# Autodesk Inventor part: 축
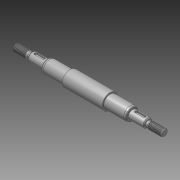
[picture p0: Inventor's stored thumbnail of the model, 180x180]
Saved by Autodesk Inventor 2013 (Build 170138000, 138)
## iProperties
Created: 2015-11
Part Number: 축
Material: 강철, 연강
Document SubType Name: Modeling
Designer: mduedu
Density: 7.86 g/cm^3
Mass: 198.507 g
Surface Area: 75.8873 cm^2
Volume: 25.2553 cm^3
Author: mduedu
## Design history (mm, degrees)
sketch "스케치1"
  geometry: L1 (-86, 0)-(86, 0); L2 (-86, 0)-(-86, 4); L3 (-86, 4)-(-70.732, 4); L4 (-70.732, 4)-(-69, 3); L5 (-69, 3)-(-67, 3); L6 (-67, 3)-(-67, 5); L7 (-67, 5)-(-49, 5); L8 (-49, 5)-(-49, 6.55); L9 (-47.355, 7.5)-(-23, 7.5); L10 (-23, 7.5)-(-23, 9); L11 (0, 0)-(0, 9); L12 (86, 4)-(70.732, 4); L13 (70.732, 4)-(69, 3); L14 (69, 3)-(67, 3); L15 (67, 3)-(67, 5); L16 (67, 5)-(49, 5); L17 (23, 7.5)-(23, 9); L18 (86, 0)-(86, 4); L19 (-23, 9)-(23, 9); L20 (-49, 6.55)-(-47.355, 7.5); L21 (47.355, 7.5)-(23, 7.5); L22 (49, 6.55)-(47.355, 7.5); L23 (49, 5)-(49, 6.55); 1 further point
  constraints: 46 end point, 10 symmetric about line, 6 perpendicular, 5 parallel, 2 midpoint, 1 coincident, 1 horizontal
  dimensions: "d0" = 172 distance of L1.start L1.end (derived); "d1" = 8 diameter of L3 L1; "d2" = 30 deg angle of L4 L5; "d3" = 6 diameter of L5 L1; "d4" = 10 diameter of L7 L1; "d5" = 15 diameter of L9 L1; "d6" = 18 diameter of L19 L1; "d8" = 18 distance of L6.end L7.end; "d9" = 46 distance of L10.end L17.end; "d10" = 2 distance of L4.end L5.end; "d11" = 17 distance from line of L4.end L2; "d16" = 13.1 diameter of L8.end L1; "d17" = 30 deg angle of L20 L9; "d18" = 26 distance between parallel lines of L10 L8
revolve "회전1" sketch "스케치1" stored, may be unused: angle "d12" = 90 deg
chamfer "모따기1" distance "d13" = 1; stored, may be unused: second distance "d14" = 2, angle "d15" = 45 deg
fillet "모깎기1" dims "d19" = 4, "d20" = 0.5
node "작업 평면1"
sketch "스케치2" dims "d23" = 12
  geometry: L1 (-4.5, 1.5)-(4.5, 1.5); L2 (4.5, 1.5)-(4.5, -1.5); L3 (4.5, -1.5)-(-4.5, -1.5); L4 (-4.5, -1.5)-(-4.5, 1.5); L5 (-9, -4)-(-9, 4) reference; 3 further points
  constraints: 8 end point, 2 midpoint, 2 parallel, 2 vertical alignment, 1 horizontal, 1 perpendicular, 4 other
  dimensions: "d21" = 3 distance between parallel lines of L3 L1; "d24" = 3 dimension on L5
extrude "돌출1" cut sketch "스케치2" distance "d25" = 1.8; taper "d26" = 0 deg
feature "스레드1" dims "d27" = 10, "d28" = 0
feature "스레드2" dims "d29" = 10, "d30" = 0
chamfer "모따기2" distance "d31" = 1; stored, may be unused: second distance "d32" = 2, angle "d33" = 45 deg
fillet "모깎기2" dims "d34" = 0.3
node "솔리드1"
mirror "대칭1"
